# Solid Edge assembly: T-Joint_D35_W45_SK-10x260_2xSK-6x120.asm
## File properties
Author: fknapp
Template: iso metric assembly.asm
Last saved by: fknapp
Revision: 9
Application: Solid Edge
Username: fknapp
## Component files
T-Joint_D35_W45.par
SK Schraube 6x120_ohne_Gewinde.par
SK Schraube 10x260_ohne_Gewinde_22042020.par
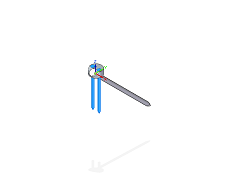
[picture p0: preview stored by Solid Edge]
